(* Logix 5000 project; controller L32E_PLC vendor 1 type 14 code 77 rev 20.13; software revision 20.00 *)

TASK MainTask (continuous, watchdog 500 ms) : MainProgram

MODULES
   Controller : vendor 1 type 14 code 77 (CompactLogixL32EController 0, rev 20.13)
      LocalENB : 1769-L32E Ethernet Port (CompactLogixL32Ethernet 1, rev 20.11)
         CM1T_Drive : ETHERNET-MODULE (Ethernet 192.168.1.50, rev 1.1, Output RPI 10 ms)
      Local : CompactBus (CompactVirtualAdapter 3, rev 20.11)
END_MODULES

TYPE CM1T_Axis :
STRUCT
   Input : SINT[36];   // Data coming from the CM1-T
   Output : SINT[28];   // Data going to the CM1-T
   us50Counter : DINT;   // Controller 50us counter
   ModeOfOperation : SINT;   // Type of motion control mode
   ModeOfOperationDisplay : SINT;   // Indicates the active control mode
   Controlword : CM1T_Controlword;   // Controls the drive operation
   DriveStatus : CM1T_DriveStatus;   // Shows status of the drive
   PositionTarget : DINT;   // Final target position for position move
   SpeedTarget : DINT;   // Maximum speed for target move
   TorqueTarget : INT;   // Max torque allowed in 0.1% of peak. Typically 1100
   AccelerationTarget : INT;   // Acceleration for profile move
   DecelerationTarget : INT;   // Deceleration for profile move
   PositionActual : DINT;   // Actual position of the drive
   TargetActual : DINT;   // 1ms position target
   PositionError : DINT;   // Error between the current drive position and the instantaneous target position
   SpeedActual : DINT;   // Actual speed of the drive
   CurrentActual : INT;   // 0.1% of rated current
   OverloadActual : INT;   // 0.1% of overload torque
   DCVoltage : INT;   // DC voltage bus. 0.1V unit
   AnalogIN : INT;   // Value of 10bit analog input
   DigitalIN : SINT;   // Read the digital inputs
   DigitalOUT : SINT;   // Set the digital outputs
   Temperature : SINT;   // Temperature of the drive
   ErrorCode : SINT;   // Indicates error in Ethernet/IP module
   ReadAddress1 : INT;   // Read Address 1
   ReadValue1 : DINT;   // Value read from register
   ReadValueAddress1 : INT;   // Responding register address
   WriteValue1 : DINT;   // Value to write
   WriteAddress1 : INT;   // Write Address 1
END_STRUCT
END_TYPE

TYPE CM1T_Controlword :
STRUCT
   Start : BOOL;   // Start a motion or set a new setpoint
   Halt : BOOL;   // Halt the current motion
   Relative_Move : BOOL;   // Execute the position profile as a relative move
   Speed_Control : BOOL;   // Execute the profile as speed control only
   Disable : BOOL;   // Disable the drive (zero torque)
   Reset_Error : BOOL;   // Reset any existing errors with rising edge
   Set_to_Zero : BOOL;   // Set the current position to 0
   Home : BOOL;   // Execute a home search
END_STRUCT
END_TYPE

TYPE CM1T_DriveStatus :
STRUCT
   StatusValue : SINT;   // Indicates status and error type
   StatusValue1 : SINT;   // Additional status values
   In_Position : BOOL;   // Drive is in position and ready to move
   Moving : BOOL;   // Drive is currently moving
   Disabled : BOOL;   // Drive is disabled
   Error : BOOL;   // Drive is in an error state
   MoveComplete : BOOL;   // Move Complete
   NewStartRequired : BOOL;   // New setpoint required
   HomeAchieved : BOOL;   // Home achieved
END_STRUCT
END_TYPE

ADD_ON_INSTRUCTION CM1T_ClearFault   (* revision 1.0, ExecuteEnableInFalse *)
// Clear Fault
VAR_IN_OUT
   CM1T_Axis : CM1T_Axis; {required}
        .CONTROLWORD.RESET_ERROR   // Reset
        .DRIVESTATUS.ERROR   // Error state
END_VAR

ROUTINE EnableInFalse   (* ladder *)
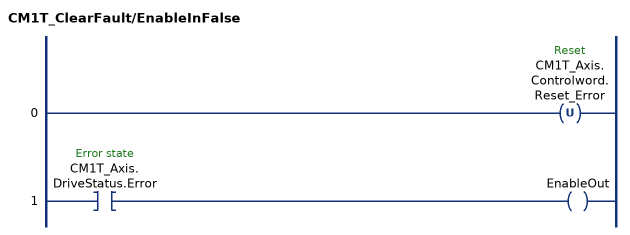
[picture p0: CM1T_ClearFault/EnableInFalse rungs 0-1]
   0: OTU(CM1T_Axis.Controlword.Reset_Error);
   1: XIC(CM1T_Axis.DriveStatus.Error)OTE(EnableOut);
END_ROUTINE

ROUTINE Logic   (* ladder *)
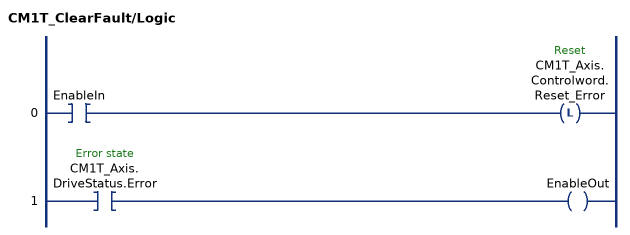
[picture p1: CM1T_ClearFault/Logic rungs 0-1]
   0: XIC(EnableIn)OTL(CM1T_Axis.Controlword.Reset_Error);
   1: XIC(CM1T_Axis.DriveStatus.Error)OTE(EnableOut);
END_ROUTINE
END_ADD_ON_INSTRUCTION

ADD_ON_INSTRUCTION CM1T_ControlMode   (* revision 1.0 *)
// Control Mode
VAR_INPUT
   ControlMode_Value : DINT; {required}
END_VAR
VAR_IN_OUT
   CM1T_Axis : CM1T_Axis; {required}
END_VAR

ROUTINE Logic   (* ladder *)
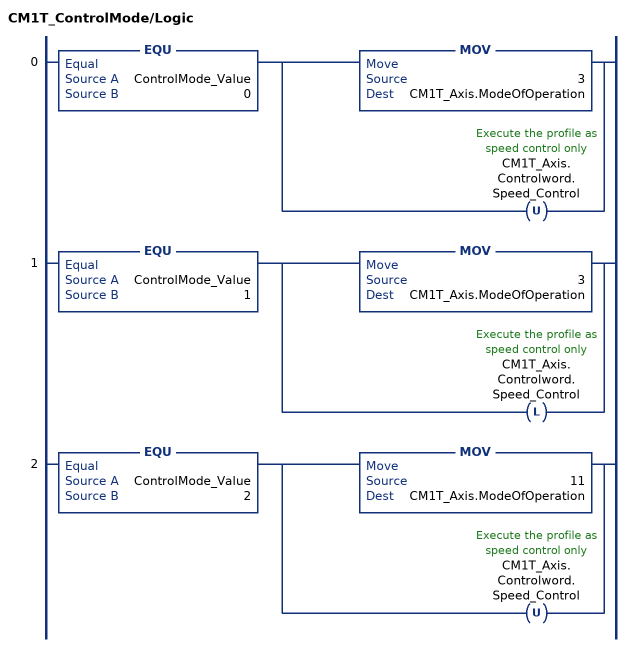
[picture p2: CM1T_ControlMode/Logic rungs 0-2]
   0: EQU(ControlMode_Value,0)[MOV(3,CM1T_Axis.ModeOfOperation) ,OTU(CM1T_Axis.Controlword.Speed_Control) ];
   1: EQU(ControlMode_Value,1)[MOV(3,CM1T_Axis.ModeOfOperation) ,OTL(CM1T_Axis.Controlword.Speed_Control) ];
   2: EQU(ControlMode_Value,2)[MOV(11,CM1T_Axis.ModeOfOperation) ,OTU(CM1T_Axis.Controlword.Speed_Control) ];
END_ROUTINE
END_ADD_ON_INSTRUCTION

ADD_ON_INSTRUCTION CM1T_DataExchange   (* revision 1.2, vendor Myostat Motion Control, ExecutePrescan *)
// CM1T Data Exchange
VAR_IN_OUT
   DriveInput : AB:ETHERNET_MODULE_SINT_36Bytes:I:0; {required}
   DriveOutput : AB:ETHERNET_MODULE_SINT_28Bytes:O:0; {required}
        .DATA[0]   // Copy outputs to drive
   CM1T_Axis : CM1T_Axis; {required}
        .OUTPUT[18]   // Write Address1
        .OUTPUT[20]   // Write Value1
        .OUTPUT[24]   // Read Address1
        .DRIVESTATUS.STATUSVALUE   // Status
        .POSITIONERROR   // Position Error
        .INPUT   // Copy input from drive
        .OUTPUT[17]   // WriteData
        .DRIVESTATUS.ERROR   // Error
        .DCVOLTAGE   // DC Voltage
        .POSITIONACTUAL   // Position
        .ANALOGIN   // AnalogIN
        .OUTPUT[0]   // PositionTarget
        .DRIVESTATUS.MOVING   // Moving
        .OUTPUT[4]   // SpeedTarget
        .CURRENTACTUAL   // Current
        .OUTPUT[8]   // TorqueTarget
        .DRIVESTATUS.IN_POSITION   // In Position
        .MODEOFOPERATIONDISPLAY   // Mode Display
        .OUTPUT[10]   // AccelerationTarget
        .OUTPUT[12]   // DecelerationTarget
        .OUTPUT[14]   // Controlword
        .OUTPUT[16]   // ModeOfOperation
        .DIGITALIN   // DigitalIN
        .OVERLOADACTUAL   // Torque
        .CONTROLWORD.START   // Controlword.Start Off
        .ERRORCODE   // ErrorCode
        .SPEEDACTUAL   // Speed
        .TEMPERATURE   // Temperature
END_VAR
VAR
   storage_InPosition : BOOL; {access None}
   rising_InPosition : BOOL; {access None}
   counter : DINT; {access None}
   old_counter : DINT; {access None}
   new_MessageCount : DINT; {access None}
END_VAR

ROUTINE Logic   (* ladder *)
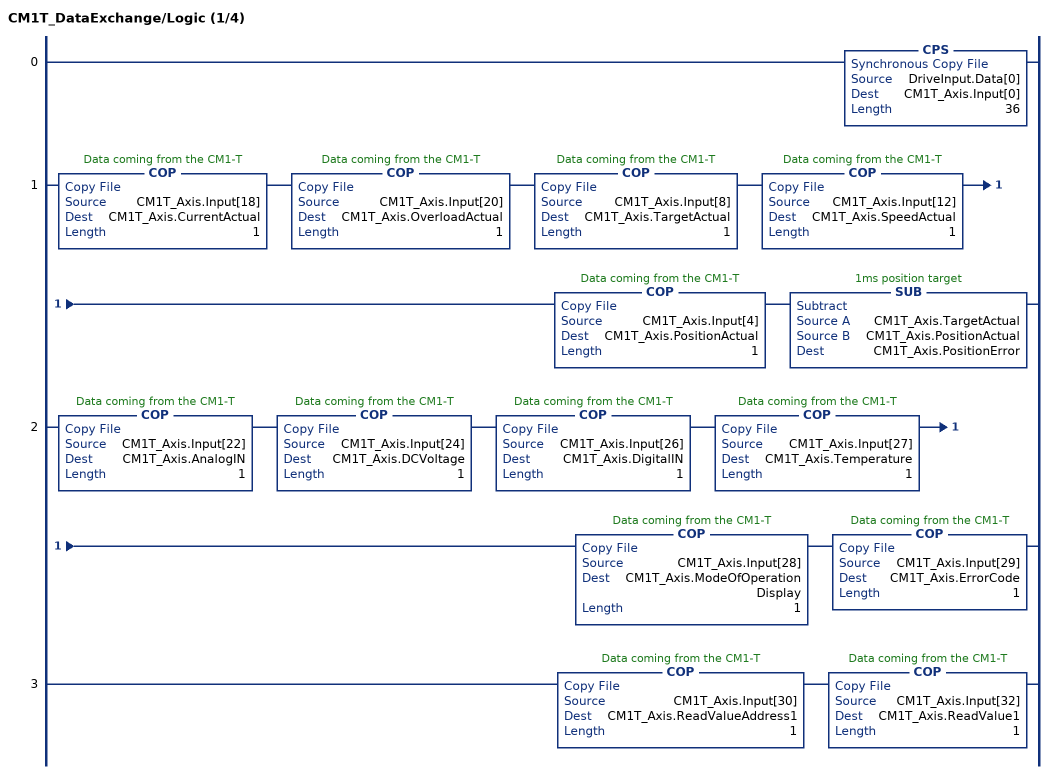
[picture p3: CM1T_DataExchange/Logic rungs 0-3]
   0: CPS(DriveInput.Data[0],CM1T_Axis.Input[0],36);
   1: COP(CM1T_Axis.Input[18],CM1T_Axis.CurrentActual,1)COP(CM1T_Axis.Input[20],CM1T_Axis.OverloadActual,1)COP(CM1T_Axis.Input[8],CM1T_Axis.TargetActual,1)COP(CM1T_Axis.Input[12],CM1T_Axis.SpeedActual,1)COP(CM1T_Axis.Input[4],CM1T_Axis.PositionActual,1)SUB(CM1T_Axis.TargetActual,CM1T_Axis.PositionActual,CM1T_Axis.PositionError);
   2: COP(CM1T_Axis.Input[22],CM1T_Axis.AnalogIN,1)COP(CM1T_Axis.Input[24],CM1T_Axis.DCVoltage,1)COP(CM1T_Axis.Input[26],CM1T_Axis.DigitalIN,1)COP(CM1T_Axis.Input[27],CM1T_Axis.Temperature,1)COP(CM1T_Axis.Input[28],CM1T_Axis.ModeOfOperationDisplay,1)COP(CM1T_Axis.Input[29],CM1T_Axis.ErrorCode,1);
   3: COP(CM1T_Axis.Input[30],CM1T_Axis.ReadValueAddress1,1)COP(CM1T_Axis.Input[32],CM1T_Axis.ReadValue1,1);
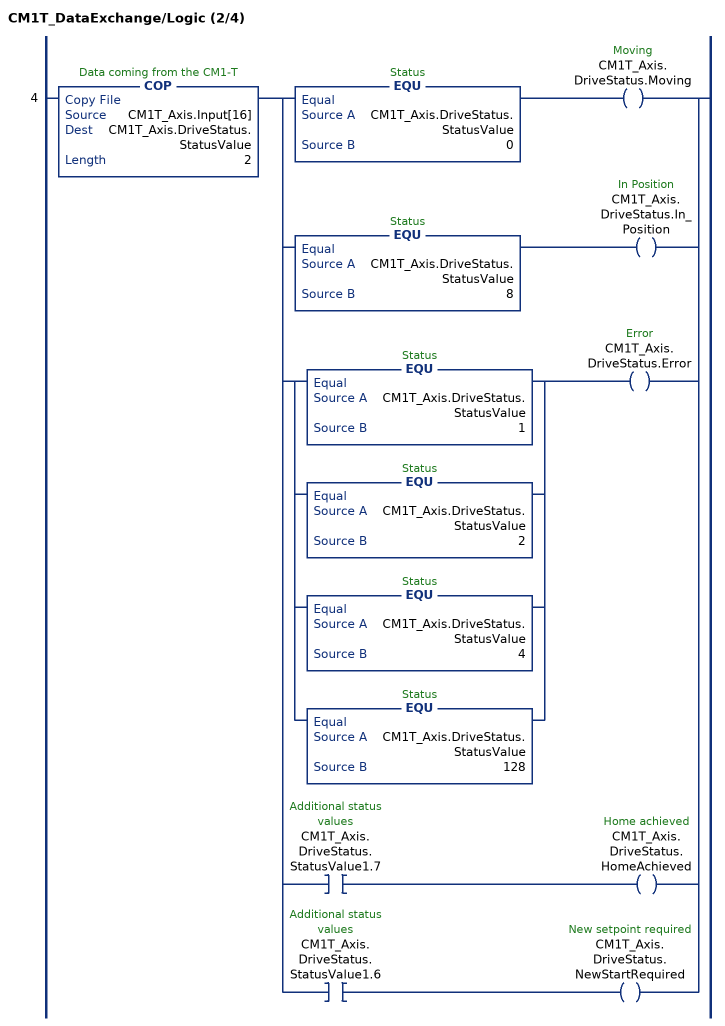
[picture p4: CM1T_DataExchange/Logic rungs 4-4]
   4: COP(CM1T_Axis.Input[16],CM1T_Axis.DriveStatus.StatusValue,2)[EQU(CM1T_Axis.DriveStatus.StatusValue,0) OTE(CM1T_Axis.DriveStatus.Moving) ,EQU(CM1T_Axis.DriveStatus.StatusValue,8) OTE(CM1T_Axis.DriveStatus.In_Position) ,[EQU(CM1T_Axis.DriveStatus.StatusValue,1) ,EQU(CM1T_Axis.DriveStatus.StatusValue,2) ,EQU(CM1T_Axis.DriveStatus.StatusValue,4) ,EQU(CM1T_Axis.DriveStatus.StatusValue,128) ] OTE(CM1T_Axis.DriveStatus.Error) ,XIC(CM1T_Axis.DriveStatus.StatusValue1.7) OTE(CM1T_Axis.DriveStatus.HomeAchieved) ,XIC(CM1T_Axis.DriveStatus.StatusValue1.6) OTE(CM1T_Axis.DriveStatus.NewStartRequired) ];
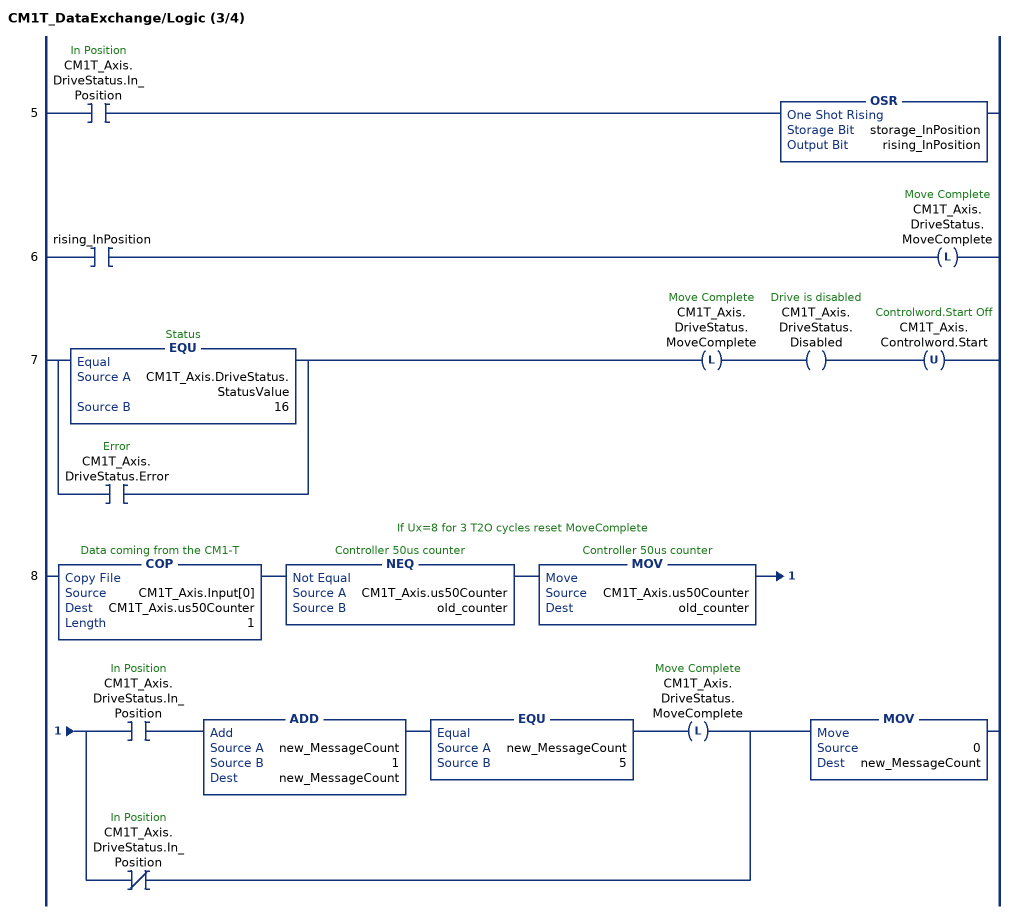
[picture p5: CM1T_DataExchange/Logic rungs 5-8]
   5: XIC(CM1T_Axis.DriveStatus.In_Position)OSR(storage_InPosition,rising_InPosition);
   6: XIC(rising_InPosition)OTL(CM1T_Axis.DriveStatus.MoveComplete);
   7: [EQU(CM1T_Axis.DriveStatus.StatusValue,16) ,XIC(CM1T_Axis.DriveStatus.Error) ]OTL(CM1T_Axis.DriveStatus.MoveComplete)OTE(CM1T_Axis.DriveStatus.Disabled)OTU(CM1T_Axis.Controlword.Start);
   // If Ux=8 for 3 T2O cycles reset MoveComplete
   8: COP(CM1T_Axis.Input[0],CM1T_Axis.us50Counter,1)NEQ(CM1T_Axis.us50Counter,old_counter)MOV(CM1T_Axis.us50Counter,old_counter)[XIC(CM1T_Axis.DriveStatus.In_Position) ADD(new_MessageCount,1,new_MessageCount) EQU(new_MessageCount,5) OTL(CM1T_Axis.DriveStatus.MoveComplete) ,XIO(CM1T_Axis.DriveStatus.In_Position) ]MOV(0,new_MessageCount);
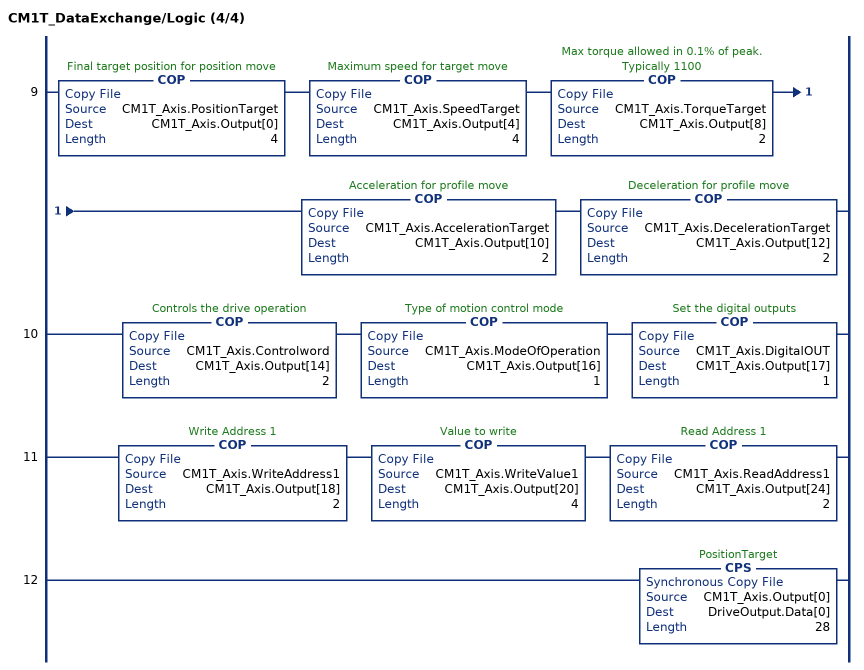
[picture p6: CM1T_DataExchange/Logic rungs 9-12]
   9: COP(CM1T_Axis.PositionTarget,CM1T_Axis.Output[0],4)COP(CM1T_Axis.SpeedTarget,CM1T_Axis.Output[4],4)COP(CM1T_Axis.TorqueTarget,CM1T_Axis.Output[8],2)COP(CM1T_Axis.AccelerationTarget,CM1T_Axis.Output[10],2)COP(CM1T_Axis.DecelerationTarget,CM1T_Axis.Output[12],2);
   10: COP(CM1T_Axis.Controlword,CM1T_Axis.Output[14],2)COP(CM1T_Axis.ModeOfOperation,CM1T_Axis.Output[16],1)COP(CM1T_Axis.DigitalOUT,CM1T_Axis.Output[17],1);
   11: COP(CM1T_Axis.WriteAddress1,CM1T_Axis.Output[18],2)COP(CM1T_Axis.WriteValue1,CM1T_Axis.Output[20],4)COP(CM1T_Axis.ReadAddress1,CM1T_Axis.Output[24],2);
   12: CPS(CM1T_Axis.Output[0],DriveOutput.Data[0],28);
END_ROUTINE

ROUTINE Prescan   (* ladder *)
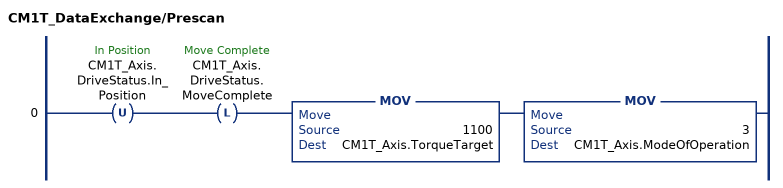
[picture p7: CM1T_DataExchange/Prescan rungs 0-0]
   0: OTU(CM1T_Axis.DriveStatus.In_Position)OTL(CM1T_Axis.DriveStatus.MoveComplete)MOV(1100,CM1T_Axis.TorqueTarget)MOV(3,CM1T_Axis.ModeOfOperation);
END_ROUTINE
END_ADD_ON_INSTRUCTION

ADD_ON_INSTRUCTION CM1T_Disable   (* revision 1.0 *)
// Disable Drive
VAR_IN_OUT
   CM1T_Axis : CM1T_Axis; {required}
END_VAR

ROUTINE Logic   (* ladder *)
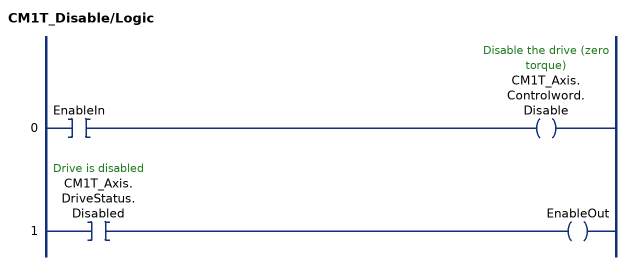
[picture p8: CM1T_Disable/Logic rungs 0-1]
   0: XIC(EnableIn)OTE(CM1T_Axis.Controlword.Disable);
   1: XIC(CM1T_Axis.DriveStatus.Disabled)OTE(EnableOut);
END_ROUTINE
END_ADD_ON_INSTRUCTION

ADD_ON_INSTRUCTION CM1T_Enable   (* revision 1.0 *)
// Enable Drive
VAR_IN_OUT
   CM1T_Axis : CM1T_Axis; {required}
END_VAR

ROUTINE Logic   (* ladder *)
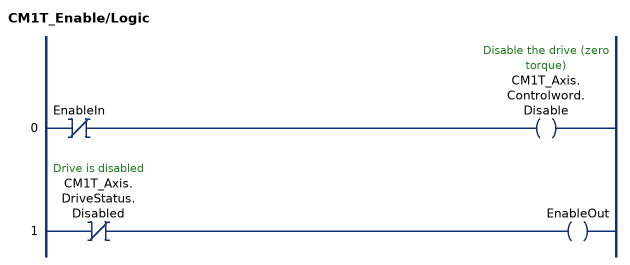
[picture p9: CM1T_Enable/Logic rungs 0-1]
   0: XIO(EnableIn)OTE(CM1T_Axis.Controlword.Disable);
   1: XIO(CM1T_Axis.DriveStatus.Disabled)OTE(EnableOut);
END_ROUTINE
END_ADD_ON_INSTRUCTION

ADD_ON_INSTRUCTION CM1T_MoveAbsolute   (* revision 1.0 *)
// Absolute Position Move
VAR_IN_OUT
   CM1T_Axis : CM1T_Axis; {required}
        .CONTROLWORD.RELATIVE_MOVE   // Set absolute move
END_VAR
VAR_INPUT
   Position : DINT; {required}
   Speed : DINT; {required}
   Acceleration : INT; {required}
   Deceleration : INT; {visible}
END_VAR

ROUTINE Logic   (* ladder *)
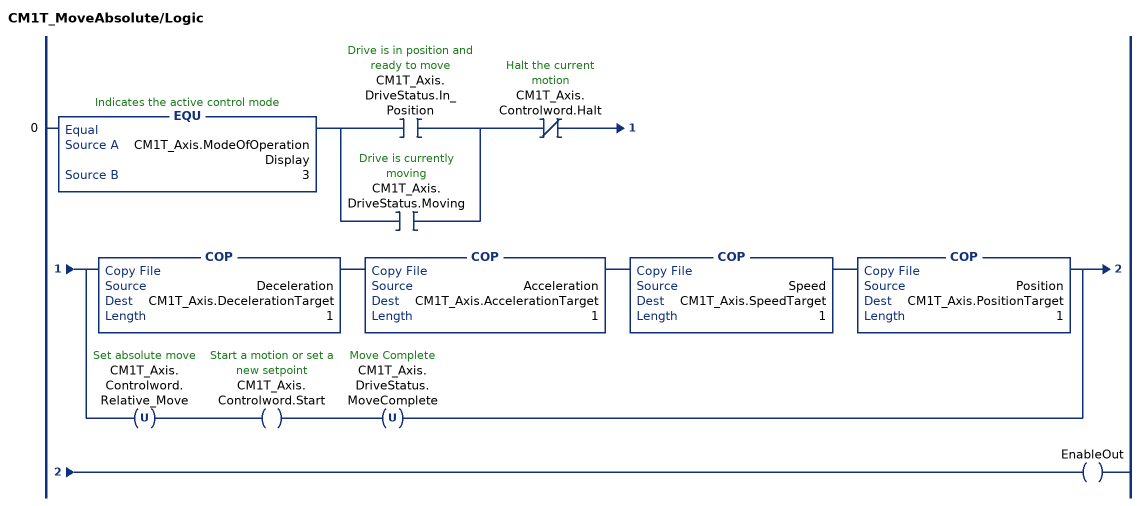
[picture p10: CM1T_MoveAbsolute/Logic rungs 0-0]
   0: EQU(CM1T_Axis.ModeOfOperationDisplay,3)[XIC(CM1T_Axis.DriveStatus.In_Position) ,XIC(CM1T_Axis.DriveStatus.Moving) ]XIO(CM1T_Axis.Controlword.Halt)[COP(Deceleration,CM1T_Axis.DecelerationTarget,1) COP(Acceleration,CM1T_Axis.AccelerationTarget,1) COP(Speed,CM1T_Axis.SpeedTarget,1) COP(Position,CM1T_Axis.PositionTarget,1) ,OTU(CM1T_Axis.Controlword.Relative_Move) OTE(CM1T_Axis.Controlword.Start) OTU(CM1T_Axis.DriveStatus.MoveComplete) ]OTE(EnableOut);
END_ROUTINE
END_ADD_ON_INSTRUCTION

ADD_ON_INSTRUCTION CM1T_MoveHome   (* revision 1.0, ExecuteEnableInFalse *)
// Homing Routine
VAR_IN_OUT
   CM1T_Axis : CM1T_Axis; {required}
END_VAR
VAR
   storage_RunHome : BOOL; {access None}
   output_RunHome : BOOL; {access None}
END_VAR

ROUTINE EnableInFalse   (* ladder *)
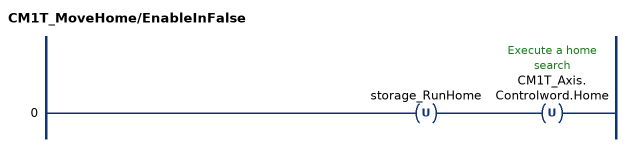
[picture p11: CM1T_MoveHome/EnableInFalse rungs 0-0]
   0: OTU(storage_RunHome)OTU(CM1T_Axis.Controlword.Home);
END_ROUTINE

ROUTINE Logic   (* ladder *)
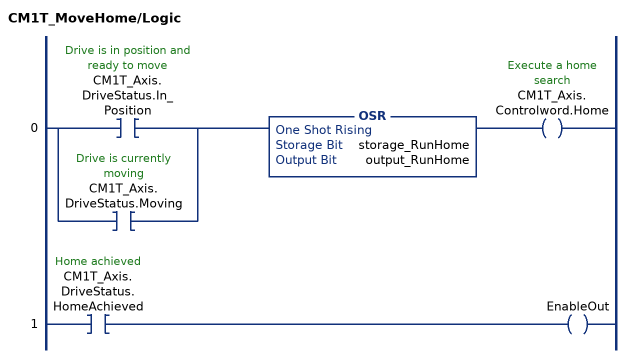
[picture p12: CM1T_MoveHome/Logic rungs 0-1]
   0: [XIC(CM1T_Axis.DriveStatus.In_Position) ,XIC(CM1T_Axis.DriveStatus.Moving) ]OSR(storage_RunHome,output_RunHome)OTE(CM1T_Axis.Controlword.Home);
   1: XIC(CM1T_Axis.DriveStatus.HomeAchieved)OTE(EnableOut);
END_ROUTINE
END_ADD_ON_INSTRUCTION

ADD_ON_INSTRUCTION CM1T_MoveRelative   (* revision 1.0 *)
// Relative Position Move
VAR_IN_OUT
   CM1T_Axis : CM1T_Axis; {required}
        .CONTROLWORD.RELATIVE_MOVE   // Set absolute move
END_VAR
VAR_INPUT
   Position : DINT; {required}
   Speed : DINT; {required}
   Acceleration : INT; {required}
   Deceleration : INT; {visible}
   Start : BOOL; {required}
END_VAR
VAR
   storage_Start : BOOL; {access None}
   output_Start : BOOL; {access None}
END_VAR

ROUTINE Logic   (* ladder *)
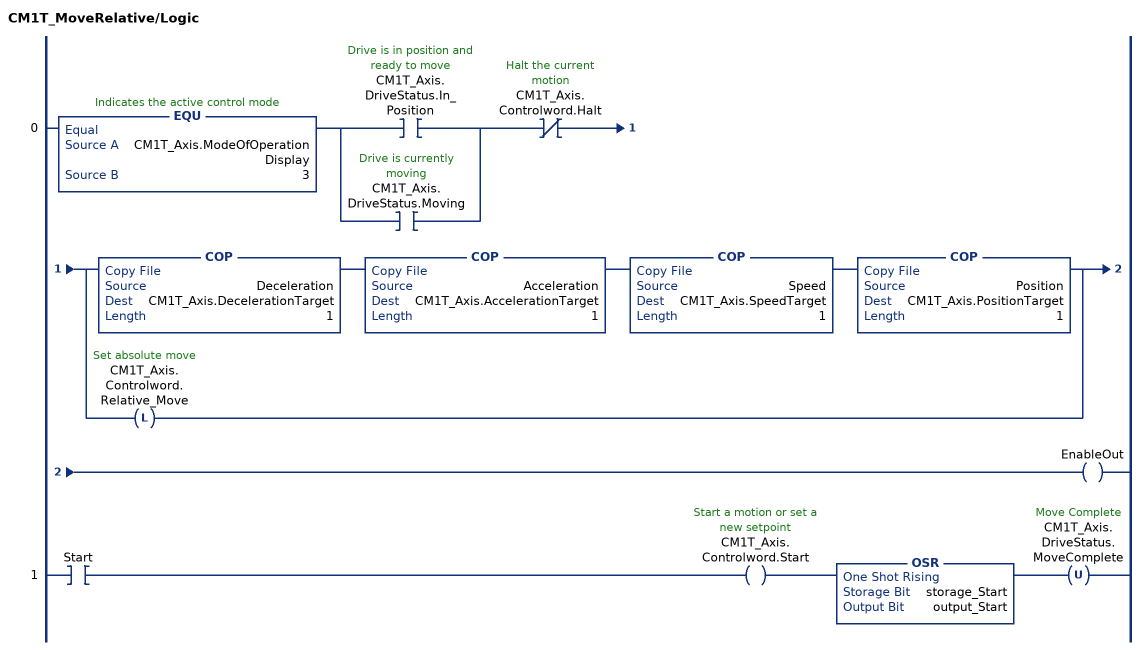
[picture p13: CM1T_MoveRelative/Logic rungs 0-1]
   0: EQU(CM1T_Axis.ModeOfOperationDisplay,3)[XIC(CM1T_Axis.DriveStatus.In_Position) ,XIC(CM1T_Axis.DriveStatus.Moving) ]XIO(CM1T_Axis.Controlword.Halt)[COP(Deceleration,CM1T_Axis.DecelerationTarget,1) COP(Acceleration,CM1T_Axis.AccelerationTarget,1) COP(Speed,CM1T_Axis.SpeedTarget,1) COP(Position,CM1T_Axis.PositionTarget,1) ,OTL(CM1T_Axis.Controlword.Relative_Move) ]OTE(EnableOut);
   1: XIC(Start)OTE(CM1T_Axis.Controlword.Start)OSR(storage_Start,output_Start)OTU(CM1T_Axis.DriveStatus.MoveComplete);
END_ROUTINE
END_ADD_ON_INSTRUCTION

ADD_ON_INSTRUCTION CM1T_MoveSpeed   (* revision 1.0 *)
// Speed Move
VAR_IN_OUT
   CM1T_Axis : CM1T_Axis; {required}
END_VAR
VAR_INPUT
   Speed : DINT; {required}
   Acceleration : DINT; {required}
   Deceleration : DINT; {required}
END_VAR

ROUTINE Logic   (* ladder *)
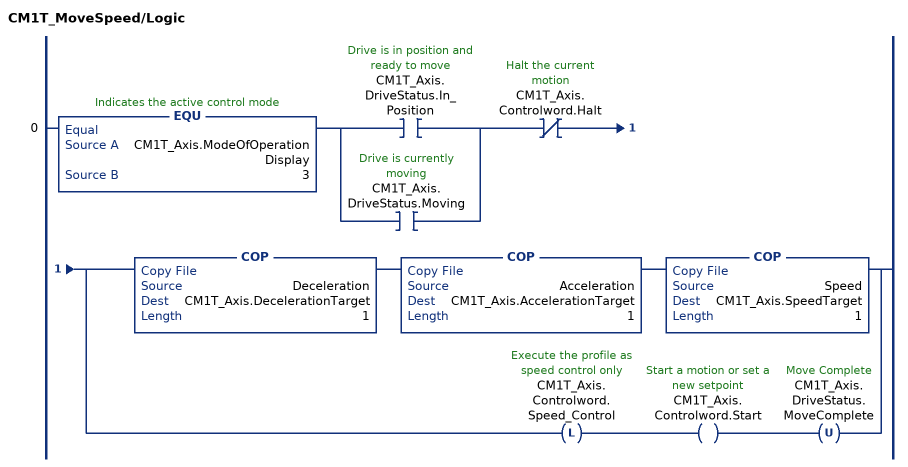
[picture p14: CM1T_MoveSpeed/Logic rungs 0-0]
   0: EQU(CM1T_Axis.ModeOfOperationDisplay,3)[XIC(CM1T_Axis.DriveStatus.In_Position) ,XIC(CM1T_Axis.DriveStatus.Moving) ]XIO(CM1T_Axis.Controlword.Halt)[COP(Deceleration,CM1T_Axis.DecelerationTarget,1) COP(Acceleration,CM1T_Axis.AccelerationTarget,1) COP(Speed,CM1T_Axis.SpeedTarget,1) ,OTL(CM1T_Axis.Controlword.Speed_Control) OTE(CM1T_Axis.Controlword.Start) OTU(CM1T_Axis.DriveStatus.MoveComplete) ];
END_ROUTINE
END_ADD_ON_INSTRUCTION

ADD_ON_INSTRUCTION CM1T_MoveTorque   (* revision 1.0 *)
// Torque Move
VAR_IN_OUT
   CM1T_Axis : CM1T_Axis; {required}
END_VAR
VAR_INPUT
   Torque : DINT; {required}
   MaxSpeed : DINT; {required}
END_VAR

ROUTINE Logic   (* ladder *)
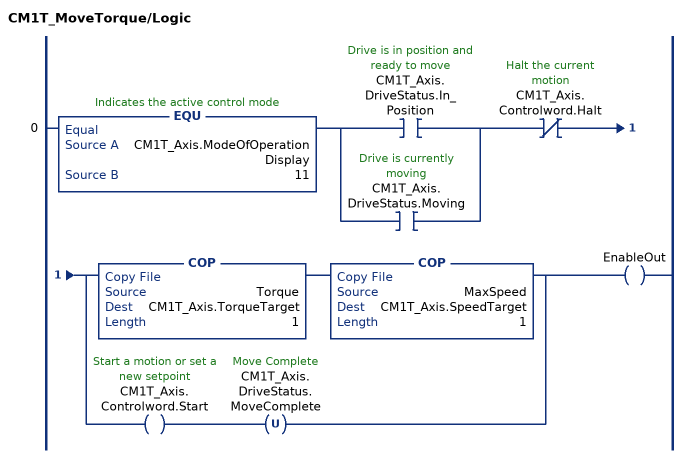
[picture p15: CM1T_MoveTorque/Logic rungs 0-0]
   0: EQU(CM1T_Axis.ModeOfOperationDisplay,11)[XIC(CM1T_Axis.DriveStatus.In_Position) ,XIC(CM1T_Axis.DriveStatus.Moving) ]XIO(CM1T_Axis.Controlword.Halt)[COP(Torque,CM1T_Axis.TorqueTarget,1) COP(MaxSpeed,CM1T_Axis.SpeedTarget,1) ,OTE(CM1T_Axis.Controlword.Start) OTU(CM1T_Axis.DriveStatus.MoveComplete) ]OTE(EnableOut);
END_ROUTINE
END_ADD_ON_INSTRUCTION

ADD_ON_INSTRUCTION CM1T_ReadRegister   (* revision 1.0 *)
// Read Register
VAR_IN_OUT
   CM1T_Axis : CM1T_Axis; {required}
END_VAR
VAR_INPUT
   Address : INT; {required}
END_VAR
VAR_OUTPUT
   Value : DINT; {access Read Only, required}
   Done : BOOL; {access Read Only, visible}
END_VAR

ROUTINE Logic   (* ladder *)
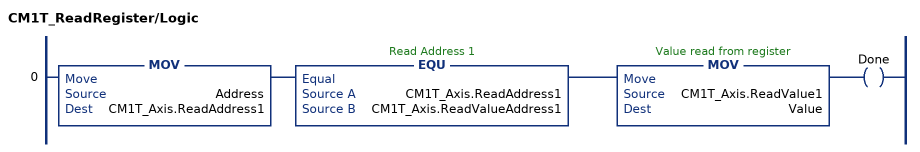
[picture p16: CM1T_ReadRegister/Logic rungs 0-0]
   0: MOV(Address,CM1T_Axis.ReadAddress1)EQU(CM1T_Axis.ReadAddress1,CM1T_Axis.ReadValueAddress1)MOV(CM1T_Axis.ReadValue1,Value)OTE(Done);
END_ROUTINE
END_ADD_ON_INSTRUCTION

ADD_ON_INSTRUCTION CM1T_WriteRegister   (* revision 1.0 *)
// WriteRegister
VAR_IN_OUT
   CM1T_Axis : CM1T_Axis; {required}
END_VAR
VAR_INPUT
   Address : INT; {required}
   Value : DINT; {access Read Only, required}
END_VAR
VAR_OUTPUT
   Done : BOOL; {access Read Only, visible}
END_VAR
VAR
   usCount : DINT; {access None}
END_VAR

ROUTINE Logic   (* ladder *)
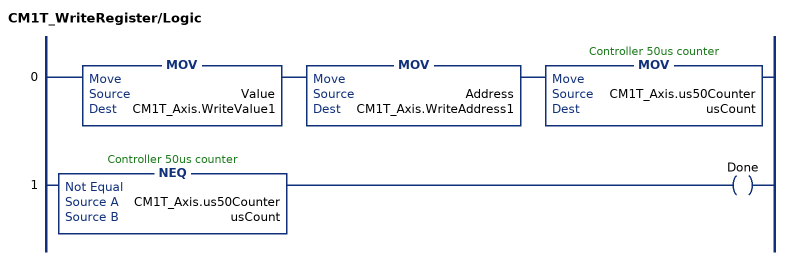
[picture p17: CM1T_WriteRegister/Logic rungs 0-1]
   0: MOV(Value,CM1T_Axis.WriteValue1)MOV(Address,CM1T_Axis.WriteAddress1)MOV(CM1T_Axis.us50Counter,usCount);
   1: NEQ(CM1T_Axis.us50Counter,usCount)OTE(Done);
END_ROUTINE
END_ADD_ON_INSTRUCTION

VAR_GLOBAL   (* controller tags *)
   MSG_Control : MESSAGE;
        MessageParameters(ServiceCode := 16#000e, DestinationTag := MSG_Response, ...)
   MSG_Response : INT;
   Query : BOOL;
END_VAR

PROGRAM MainProgram   (* main routine MainRoutine *)
VAR
   ClearFault : BOOL;
   CM1T_1 : CM1T_Axis;
   DisableDrive : BOOL;
   FB_CM1T_ClearFault : CM1T_ClearFault;
   FB_CM1T_ControlMode : CM1T_ControlMode;
   FB_CM1T_DataExchange : CM1T_DataExchange;
   FB_CM1T_Disable : CM1T_Disable;
   FB_CM1T_Enable : CM1T_Enable;
   FB_CM1T_MoveAbsolute : CM1T_MoveAbsolute;
   FB_CM1T_MoveHome : CM1T_MoveHome;
   FB_CM1T_MoveRelative : CM1T_MoveRelative;
   FB_CM1T_MoveSpeed : CM1T_MoveSpeed;
   FB_CM1T_MoveTorque : CM1T_MoveTorque;
   FB_CM1T_ReadRegister : CM1T_ReadRegister;   // Read V9
   FB_CM1T_WriteRegister : CM1T_WriteRegister;   // Write to speed to V9
   Halt : BOOL;
   Home : BOOL;
   NextPosition : SINT;
   RunAbsolute : BOOL;
   RunRelative : BOOL;
   RunSpeed : BOOL;
   RunTorque : BOOL;
   Speed : DINT;
   StartRelative : BOOL;
   Torque : DINT;
   V9 : DINT;
END_VAR

ROUTINE MainRoutine   (* ladder *)
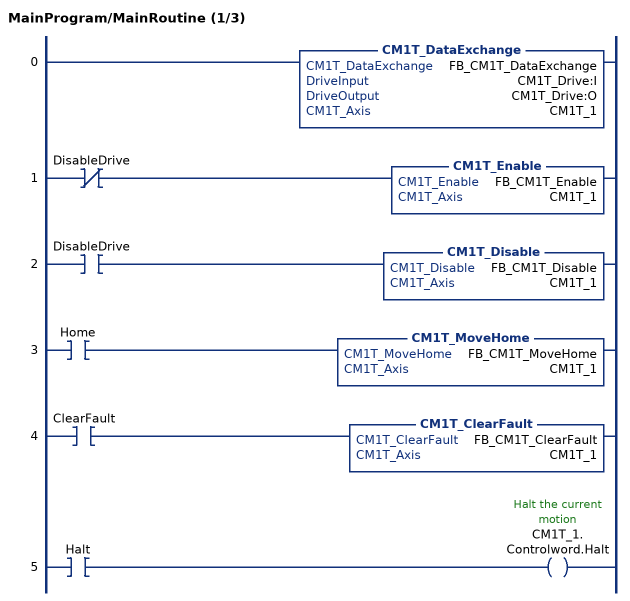
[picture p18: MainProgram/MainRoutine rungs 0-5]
   0: CM1T_DataExchange(FB_CM1T_DataExchange,CM1T_Drive:I,CM1T_Drive:O,CM1T_1);
   1: XIO(DisableDrive)CM1T_Enable(FB_CM1T_Enable,CM1T_1);
   2: XIC(DisableDrive)CM1T_Disable(FB_CM1T_Disable,CM1T_1);
   3: XIC(Home)CM1T_MoveHome(FB_CM1T_MoveHome,CM1T_1);
   4: XIC(ClearFault)CM1T_ClearFault(FB_CM1T_ClearFault,CM1T_1);
   5: XIC(Halt)OTE(CM1T_1.Controlword.Halt);
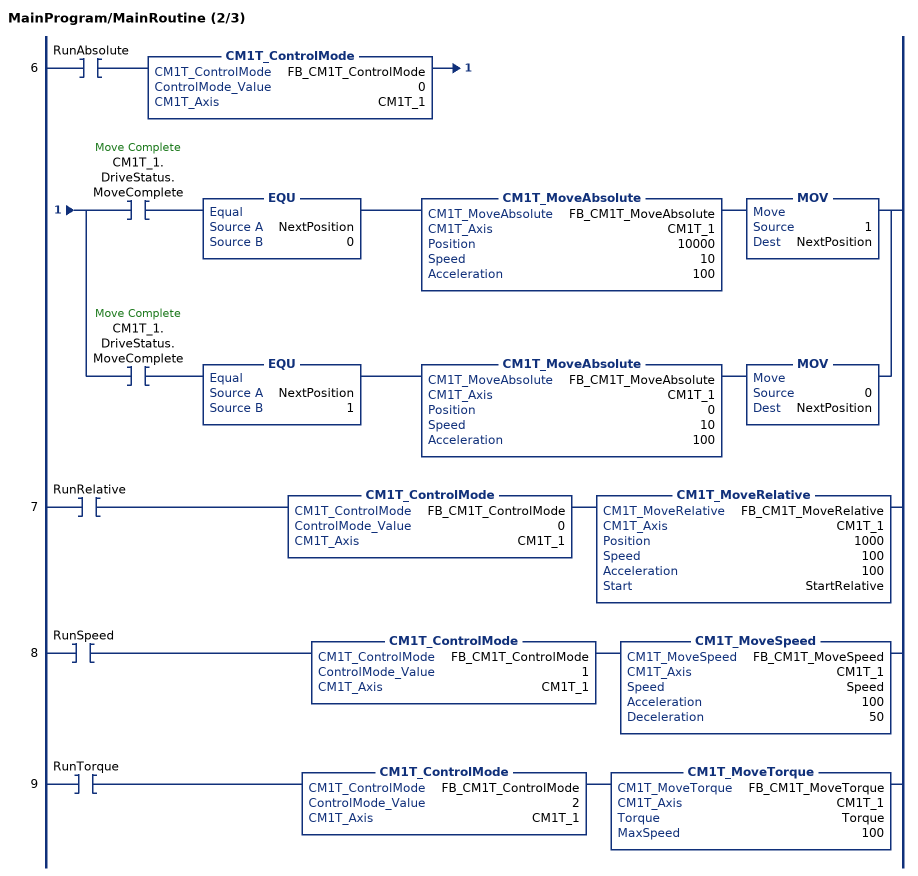
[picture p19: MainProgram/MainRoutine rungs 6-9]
   6: XIC(RunAbsolute)CM1T_ControlMode(FB_CM1T_ControlMode,0,CM1T_1)[XIC(CM1T_1.DriveStatus.MoveComplete) EQU(NextPosition,0) CM1T_MoveAbsolute(FB_CM1T_MoveAbsolute,CM1T_1,10000,10,100) MOV(1,NextPosition) ,XIC(CM1T_1.DriveStatus.MoveComplete) EQU(NextPosition,1) CM1T_MoveAbsolute(FB_CM1T_MoveAbsolute,CM1T_1,0,10,100) MOV(0,NextPosition) ];
   7: XIC(RunRelative)CM1T_ControlMode(FB_CM1T_ControlMode,0,CM1T_1)CM1T_MoveRelative(FB_CM1T_MoveRelative,CM1T_1,1000,100,100,StartRelative);
   8: XIC(RunSpeed)CM1T_ControlMode(FB_CM1T_ControlMode,1,CM1T_1)CM1T_MoveSpeed(FB_CM1T_MoveSpeed,CM1T_1,Speed,100,50);
   9: XIC(RunTorque)CM1T_ControlMode(FB_CM1T_ControlMode,2,CM1T_1)CM1T_MoveTorque(FB_CM1T_MoveTorque,CM1T_1,Torque,100);
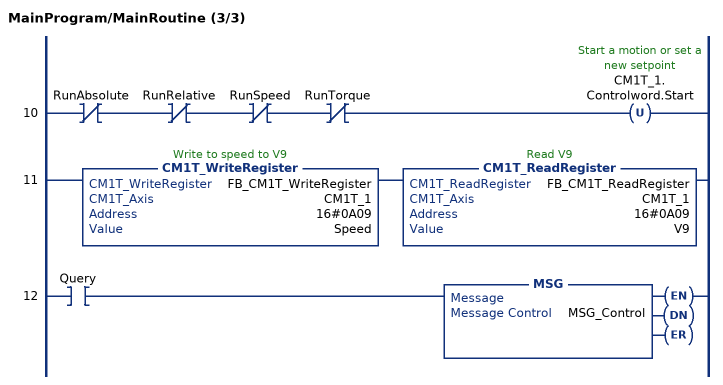
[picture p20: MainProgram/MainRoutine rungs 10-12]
   10: XIO(RunAbsolute)XIO(RunRelative)XIO(RunSpeed)XIO(RunTorque)OTU(CM1T_1.Controlword.Start);
   11: CM1T_WriteRegister(FB_CM1T_WriteRegister,CM1T_1,16#0A09,Speed)CM1T_ReadRegister(FB_CM1T_ReadRegister,CM1T_1,16#0A09,V9);
   12: XIC(Query)MSG(MSG_Control);
END_ROUTINE
END_PROGRAM
